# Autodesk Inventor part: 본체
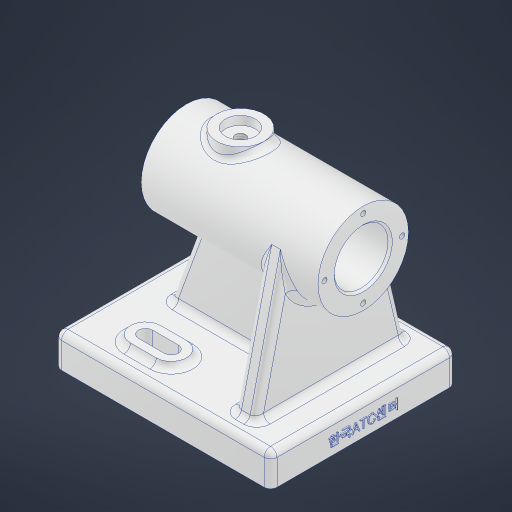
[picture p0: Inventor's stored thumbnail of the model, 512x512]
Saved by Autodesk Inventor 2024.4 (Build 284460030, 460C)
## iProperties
Created: 2026-09
Part Number: 본체
Material: 알루미늄 6061
Document SubType Name: Modeling
Designer: user
Density: 2.7 g/cm^3
Appearance: 알루미늄 - 평지
Mass: 631.369 g
Surface Area: 514.041 cm^2
Volume: 233.84 cm^3
Author: user
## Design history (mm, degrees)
sketch "스케치1"
  geometry: L1 (-41, 0)-(41, 0); L2 (-41, 21)-(41, 21); L3 (41, 21)-(41, 12.5); L4 (41, 12.5)-(21, 12.5); L5 (21, 12.5)-(21, 14.5); L6 (21, 14.5)-(-41, 14.5); L7 (-41, 14.5)-(-41, 21); L8 (-59, -57)-(41, -57); L9 (41, -57)-(41, -72); L10 (41, -72)-(-59, -72); L11 (-59, -72)-(-59, -57); 2 further points
  constraints: 22 end point, 5 perpendicular, 3 horizontal, 3 parallel, 3 point on line, 1 coincident, 1 midpoint
  dimensions: "d0" = 82 distance of L1.start L1.end; "d1" = 42 diameter of L2 L1; "d2" = 29 diameter of L6 L1; "d3" = 25 diameter of L4 L1; "d4" = 62 distance between parallel lines of L5 L7; "d5" = 100 distance between parallel lines of L9 L11; "d6" = 144 diameter of L10 L1; "d7" = 15 distance between parallel lines of L8 L10
revolve "회전1" stored, may be unused: angle "d8" = 90 deg
extrude "돌출1" join sketch "스케치1" stored distance "d9" = 86; taper "d10" = 0 deg
node "작업 평면1"
sketch "스케치3"
  geometry: L1 (86, 15)-(0, 15) reference; L2 (0, 15)-(0, 0) reference; L3 (86, 0)-(86, 15) reference; L4 (22.559, 76.814)-(8, 15); L5 (63.441, 76.814)-(78, 15); A1 r 21 centre (43, 72) between (22.559, 76.814) and (63.441, 76.814) reference; 1 further point
  constraints: 4 end point, 2 point on circle, 2 point on line, 2 tangent
  dimensions: "d18" = 8 distance of L4.end L1.end; "d19" = 8 distance of L1.start L5.end
extrude "돌출2" join sketch "스케치3" distance "d20" = 10; taper "d21" = 0 deg
sketch "스케치4"
  geometry: L1 (-59, -57)-(41, -57) reference; L2 (-44, -57)-(-30.897, -21); L3 (-41, -21)-(41, -21) reference; L4 (-59, -72)-(-59, -57) reference; 1 further point
  constraints: 2 end point, 2 point on line
  dimensions: "d22" = 15 distance from line of L2.start L4; "d23" = 70 deg angle of L1 L2
feature "리브1" sketch "스케치4" dims "d24" = 1, "d25" = 10, "d26" = 0, "d27" = 0, "d28" = 1, "d29" = 1
sketch "스케치5" dims "d37" = 36
  geometry: C1 r 21 at (0, 0) reference; 3 further points
  constraints: 2 vertical alignment, 1 coincident, 2 other
hole "구멍1" sketch "스케치5" at (0, 18) diameter "d30" = 2.459; stored, may be unused: countersink angle "d34" = 90 deg, drill point angle "d36" = 118 deg; dims "d31" = 8, "d32" = 4, "d33" = 2, "d35" = 10
node "작업 평면2"
chamfer "모따기1" distance "d41" = 1; stored, may be unused: second distance "d42" = 2, angle "d43" = 45 deg
sketch "스케치6"
  geometry: L1 (0, 0)-(100, 0) reference; L2 (0, 0)-(0, -86) reference; L3 (26, -16)-(38, -16); L4 (26, -23)-(38, -23); L5 (38, -9)-(26, -9); L6 (26, -70)-(38, -70); L7 (26, -77)-(38, -77); L8 (38, -63)-(26, -63); A1 r 7 centre (26, -16) between (26, -9) and (26, -23); A2 r 7 centre (38, -16) between (38, -23) and (38, -9); A3 r 7 centre (26, -70) between (26, -63) and (26, -77); A4 r 7 centre (38, -70) between (38, -77) and (38, -63); 3 further points
  constraints: 16 end point, 8 point on circle, 8 tangent, 4 centre point, 3 parallel, 2 midpoint, 1 horizontal, 1 vertical alignment
  dimensions: "d44" = 12 distance of L6.end L6.start; "d45" = 12 distance of L3.end L3.start; "d46" = 54 distance of point (32, -16) point (32, -70); "d47" = 26 distance from line of L6.start L2; "d48" = 16 distance from line of L1 point (32, -16); "d52" = 14 distance between parallel lines of L5 L4; "d53" = 14 distance between parallel lines of L8 L7
extrude "돌출3" join sketch "스케치6" distance "d49" = 3; taper "d50" = 0 deg
sketch "스케치7"
  geometry: L1 (26, -77)-(38, -77) reference; L2 (26, -70)-(38, -70); L3 (26, -66.7)-(38, -66.7); L4 (38, -73.3)-(26, -73.3); A1 r 7 centre (38, -70) between (38, -77) and (38, -63) reference; A2 r 7 centre (26, -70) between (26, -63) and (26, -77) reference; A3 r 3.3 centre (26, -70) between (26, -66.7) and (26, -73.3); A4 r 3.3 centre (38, -70) between (38, -73.3) and (38, -66.7); 2 further points
  constraints: 8 end point, 4 point on circle, 4 tangent, 2 centre point, 2 parallel, 1 midpoint
  dimensions: "d51" = 6.6 distance between parallel lines of L3 L4
extrude "돌출4" cut sketch "스케치7" extent not by distance; stored distance "d54" = 0; taper "d55" = 0 deg
fillet "모깎기1" dims "d56" = 3
node "작업 평면3"
sketch "스케치8"
  geometry: L1 (15, -64)-(15, -22) reference; C1 r 11 at (40, -43); 1 further point
  constraints: 1 centre point
  dimensions: "d58" = 25 distance from line of C1.centre L1; "d59" = 22 diameter of C1
extrude "돌출5" join sketch "스케치8" stored distance "d60" = 10; taper "d61" = 0 deg
sketch "스케치9"
  geometry: C1 r 11 at (0, 0) reference; 2 further points
  constraints: 1 coincident
hole "구멍2" sketch "스케치9" at (0, 0) diameter "d62" = 4.917; stored, may be unused: countersink angle "d66" = 90 deg, drill point angle "d68" = 118 deg; dims "d63" = 12, "d64" = 14, "d65" = 4, "d67" = 17.1
fillet "모깎기2" dims "d69" = 3
fillet "모깎기3" dims "d70" = 3
fillet "모깎기4" dims "d71" = 3
fillet "모깎기5" dims "d72" = 3
fillet "모깎기6" dims "d73" = 3
sketch "스케치10"
  geometry: L1 (80, 0)-(0, 0) reference; 2 further points
  constraints: 1 vertical alignment, 1 other
  dimensions: "d74" = 6 distance from line of point (40, 6) L1
feature "엠보싱1" sketch "스케치10" dims "d75" = 0.5, "d76" = 0
fillet "모깎기7" dims "d77" = 3
node "솔리드1"
pattern_circular "원형 패턴1" dims angle "d39" = 360 deg
mirror "미러1"
mirror "미러2"
feature "A9D066F2-1C7D-4E18-AEED-F7BC21143FA4" dims "d62" = 4.917, "d63" = 12, "d64" = 14, "d65" = 4, "d66" = 90 deg, "d67" = 17.1, "d68" = 118 deg
other parameters: "d15" = -15, "d57" = -96
